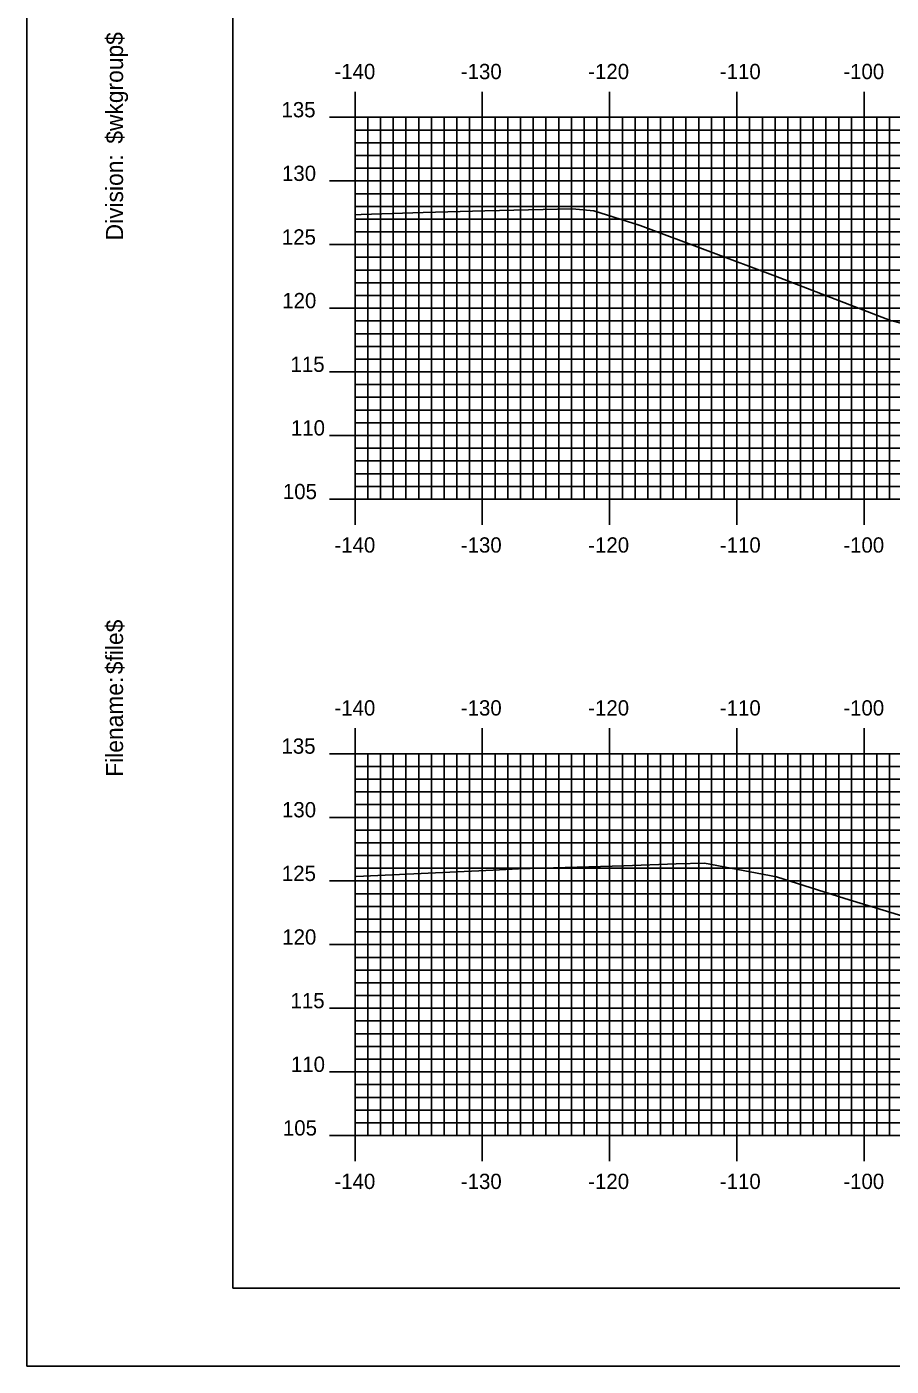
# Model space of a CAD drawing. Extents: x 854681 to 855024, y 366605 to 366825.
# Drawn here: x 854680.8 to 854748.7, y 366604.9 to 366710.2 of the extents above; entities that cross this region are included whole.
import ezdxf

# ---------------------------------------------------------------- set-up
doc = ezdxf.new("R2010")
doc.units = 0
for name, color, linetype in [('BORDER', 7, 'Continuous'), ('H_V ANNOTATION', 7, 'Continuous'), ('M_Roadway_Centerline', 7, 'Continuous'), ('MAJOR', 7, 'Continuous'), ('MINOR', 7, 'Continuous'), ('PLOT BOUNDARY', 7, 'Continuous'), ('S_Roadway_Centerline', 7, 'Continuous')]:
    doc.layers.add(name, color=color, linetype=linetype)

msp = doc.modelspace()

# ---------------------------------------------------------------- linework, layer by layer
at = {"layer": 'BORDER'}
msp.add_lwpolyline([(854696.96, 366611.06), (855016.96, 366611.06), (855016.96, 366821.06), (854696.96, 366821.06)], close=True, dxfattribs=at)
at = {"layer": 'MAJOR'}
for p, q in [((854706.56, 366705.06), (854706.56, 366703.06)), ((854716.56, 366705.06), (854716.56, 366703.06)), ((854726.56, 366705.06), (854726.56, 366703.06)), ((854736.56, 366705.06), (854736.56, 366703.06)), ((854746.56, 366705.06), (854746.56, 366703.06)), ((854704.55, 366703.06), (854706.56, 366703.06)), ((854706.56, 366703.06), (854986.56, 366703.06)), ((854706.56, 366673.06), (854706.56, 366703.06)), ((854706.56, 366673.06), (854706.56, 366703.06)), ((854706.56, 366703.06), (854986.56, 366703.06)), ((854716.56, 366673.06), (854716.56, 366703.06)), ((854726.56, 366673.06), (854726.56, 366703.06)), ((854736.56, 366673.06), (854736.56, 366703.06)), ((854746.56, 366673.06), (854746.56, 366703.06)), ((854704.55, 366698.06), (854706.56, 366698.06)), ((854706.56, 366698.06), (854986.56, 366698.06)), ((854704.55, 366693.06), (854706.56, 366693.06)), ((854706.56, 366693.06), (854986.56, 366693.06)), ((854704.55, 366688.06), (854706.56, 366688.06)), ((854706.56, 366688.06), (854986.56, 366688.06)), ((854704.55, 366683.06), (854706.56, 366683.06)), ((854706.56, 366683.06), (854986.56, 366683.06)), ((854704.55, 366678.06), (854706.56, 366678.06)), ((854706.56, 366678.06), (854986.56, 366678.06)), ((854704.55, 366673.06), (854706.56, 366673.06)), ((854706.56, 366673.06), (854986.56, 366673.06)), ((854706.56, 366673.06), (854986.56, 366673.06)), ((854706.56, 366671.05), (854706.56, 366673.06)), ((854716.56, 366671.05), (854716.56, 366673.06)), ((854726.56, 366671.05), (854726.56, 366673.06)), ((854736.56, 366671.05), (854736.56, 366673.06)), ((854746.56, 366671.05), (854746.56, 366673.06)), ((854706.56, 366655.06), (854706.56, 366653.06)), ((854716.56, 366655.06), (854716.56, 366653.06)), ((854726.56, 366655.06), (854726.56, 366653.06)), ((854736.56, 366655.06), (854736.56, 366653.06)), ((854746.56, 366655.06), (854746.56, 366653.06)), ((854704.55, 366653.06), (854706.56, 366653.06)), ((854706.56, 366653.06), (854986.56, 366653.06)), ((854706.56, 366623.06), (854706.56, 366653.06)), ((854706.56, 366623.06), (854706.56, 366653.06)), ((854706.56, 366653.06), (854986.56, 366653.06)), ((854716.56, 366623.06), (854716.56, 366653.06)), ((854726.56, 366623.06), (854726.56, 366653.06)), ((854736.56, 366623.06), (854736.56, 366653.06)), ((854746.56, 366623.06), (854746.56, 366653.06)), ((854704.55, 366648.06), (854706.56, 366648.06)), ((854706.56, 366648.06), (854986.56, 366648.06)), ((854704.55, 366643.06), (854706.56, 366643.06)), ((854706.56, 366643.06), (854986.56, 366643.06)), ((854704.55, 366638.06), (854706.56, 366638.06)), ((854706.56, 366638.06), (854986.56, 366638.06)), ((854704.55, 366633.06), (854706.56, 366633.06)), ((854706.56, 366633.06), (854986.56, 366633.06)), ((854704.55, 366628.06), (854706.56, 366628.06)), ((854706.56, 366628.06), (854986.56, 366628.06)), ((854704.55, 366623.06), (854706.56, 366623.06)), ((854706.56, 366623.06), (854986.56, 366623.06)), ((854706.56, 366623.06), (854986.56, 366623.06)), ((854706.56, 366621.05), (854706.56, 366623.06)), ((854716.56, 366621.05), (854716.56, 366623.06)), ((854726.56, 366621.05), (854726.56, 366623.06)), ((854736.56, 366621.05), (854736.56, 366623.06)), ((854746.56, 366621.05), (854746.56, 366623.06))]:
    msp.add_line(p, q, dxfattribs=at)
at = {"layer": 'MINOR'}
for p, q in [((854707.56, 366673.06), (854707.56, 366703.06)), ((854708.56, 366673.06), (854708.56, 366703.06)), ((854709.56, 366673.06), (854709.56, 366703.06)), ((854710.56, 366673.06), (854710.56, 366703.06)), ((854711.56, 366673.06), (854711.56, 366703.06)), ((854712.56, 366673.06), (854712.56, 366703.06)), ((854713.56, 366673.06), (854713.56, 366703.06)), ((854714.56, 366673.06), (854714.56, 366703.06)), ((854715.56, 366673.06), (854715.56, 366703.06)), ((854717.56, 366673.06), (854717.56, 366703.06)), ((854718.56, 366673.06), (854718.56, 366703.06)), ((854719.56, 366673.06), (854719.56, 366703.06)), ((854720.56, 366673.06), (854720.56, 366703.06)), ((854721.56, 366673.06), (854721.56, 366703.06)), ((854722.56, 366673.06), (854722.56, 366703.06)), ((854723.56, 366673.06), (854723.56, 366703.06)), ((854724.56, 366673.06), (854724.56, 366703.06)), ((854725.56, 366673.06), (854725.56, 366703.06)), ((854727.56, 366673.06), (854727.56, 366703.06)), ((854728.56, 366673.06), (854728.56, 366703.06)), ((854729.56, 366673.06), (854729.56, 366703.06)), ((854730.56, 366673.06), (854730.56, 366703.06)), ((854731.56, 366673.06), (854731.56, 366703.06)), ((854732.56, 366673.06), (854732.56, 366703.06)), ((854733.56, 366673.06), (854733.56, 366703.06)), ((854734.56, 366673.06), (854734.56, 366703.06)), ((854735.56, 366673.06), (854735.56, 366703.06)), ((854737.56, 366673.06), (854737.56, 366703.06)), ((854738.56, 366673.06), (854738.56, 366703.06)), ((854739.56, 366673.06), (854739.56, 366703.06)), ((854740.56, 366673.06), (854740.56, 366703.06)), ((854741.56, 366673.06), (854741.56, 366703.06)), ((854742.56, 366673.06), (854742.56, 366703.06)), ((854743.56, 366673.06), (854743.56, 366703.06)), ((854744.56, 366673.06), (854744.56, 366703.06)), ((854745.56, 366673.06), (854745.56, 366703.06)), ((854747.56, 366673.06), (854747.56, 366703.06)), ((854748.56, 366673.06), (854748.56, 366703.06)), ((854706.56, 366702.06), (854986.56, 366702.06)), ((854706.56, 366702.06), (854708.56, 366702.06)), ((854706.56, 366701.06), (854986.56, 366701.06)), ((854706.56, 366701.06), (854708.56, 366701.06)), ((854706.56, 366700.06), (854986.56, 366700.06)), ((854706.56, 366700.06), (854708.56, 366700.06)), ((854706.56, 366699.06), (854986.56, 366699.06)), ((854706.56, 366699.06), (854708.56, 366699.06)), ((854706.56, 366697.06), (854986.56, 366697.06)), ((854706.56, 366697.06), (854708.56, 366697.06)), ((854706.56, 366696.06), (854986.56, 366696.06)), ((854706.56, 366696.06), (854708.56, 366696.06)), ((854706.56, 366695.06), (854986.56, 366695.06)), ((854706.56, 366695.06), (854708.56, 366695.06)), ((854706.56, 366694.06), (854986.56, 366694.06)), ((854706.56, 366694.06), (854708.56, 366694.06)), ((854706.56, 366692.06), (854986.56, 366692.06)), ((854706.56, 366692.06), (854708.56, 366692.06)), ((854706.56, 366691.06), (854986.56, 366691.06)), ((854706.56, 366691.06), (854708.56, 366691.06)), ((854706.56, 366690.06), (854986.56, 366690.06)), ((854706.56, 366690.06), (854708.56, 366690.06)), ((854706.56, 366689.06), (854986.56, 366689.06)), ((854706.56, 366689.06), (854708.56, 366689.06)), ((854706.56, 366687.06), (854986.56, 366687.06)), ((854706.56, 366687.06), (854708.56, 366687.06)), ((854706.56, 366686.06), (854986.56, 366686.06)), ((854706.56, 366686.06), (854708.56, 366686.06)), ((854706.56, 366685.06), (854986.56, 366685.06)), ((854706.56, 366685.06), (854708.56, 366685.06)), ((854706.56, 366684.06), (854986.56, 366684.06)), ((854706.56, 366684.06), (854708.56, 366684.06)), ((854706.56, 366682.06), (854986.56, 366682.06)), ((854706.56, 366682.06), (854708.56, 366682.06)), ((854706.56, 366681.06), (854986.56, 366681.06)), ((854706.56, 366681.06), (854708.56, 366681.06)), ((854706.56, 366680.06), (854986.56, 366680.06)), ((854706.56, 366680.06), (854708.56, 366680.06)), ((854706.56, 366679.06), (854986.56, 366679.06)), ((854706.56, 366679.06), (854708.56, 366679.06)), ((854706.56, 366677.06), (854986.56, 366677.06)), ((854706.56, 366677.06), (854708.56, 366677.06)), ((854706.56, 366676.06), (854986.56, 366676.06)), ((854706.56, 366676.06), (854708.56, 366676.06)), ((854706.56, 366675.06), (854986.56, 366675.06)), ((854706.56, 366675.06), (854708.56, 366675.06)), ((854706.56, 366674.06), (854986.56, 366674.06)), ((854706.56, 366674.06), (854708.56, 366674.06)), ((854707.56, 366623.06), (854707.56, 366653.06)), ((854708.56, 366623.06), (854708.56, 366653.06)), ((854709.56, 366623.06), (854709.56, 366653.06)), ((854710.56, 366623.06), (854710.56, 366653.06)), ((854711.56, 366623.06), (854711.56, 366653.06)), ((854712.56, 366623.06), (854712.56, 366653.06)), ((854713.56, 366623.06), (854713.56, 366653.06)), ((854714.56, 366623.06), (854714.56, 366653.06)), ((854715.56, 366623.06), (854715.56, 366653.06)), ((854717.56, 366623.06), (854717.56, 366653.06)), ((854718.56, 366623.06), (854718.56, 366653.06)), ((854719.56, 366623.06), (854719.56, 366653.06)), ((854720.56, 366623.06), (854720.56, 366653.06)), ((854721.56, 366623.06), (854721.56, 366653.06)), ((854722.56, 366623.06), (854722.56, 366653.06)), ((854723.56, 366623.06), (854723.56, 366653.06)), ((854724.56, 366623.06), (854724.56, 366653.06)), ((854725.56, 366623.06), (854725.56, 366653.06)), ((854727.56, 366623.06), (854727.56, 366653.06)), ((854728.56, 366623.06), (854728.56, 366653.06)), ((854729.56, 366623.06), (854729.56, 366653.06)), ((854730.56, 366623.06), (854730.56, 366653.06)), ((854731.56, 366623.06), (854731.56, 366653.06)), ((854732.56, 366623.06), (854732.56, 366653.06)), ((854733.56, 366623.06), (854733.56, 366653.06)), ((854734.56, 366623.06), (854734.56, 366653.06)), ((854735.56, 366623.06), (854735.56, 366653.06)), ((854737.56, 366623.06), (854737.56, 366653.06)), ((854738.56, 366623.06), (854738.56, 366653.06)), ((854739.56, 366623.06), (854739.56, 366653.06)), ((854740.56, 366623.06), (854740.56, 366653.06)), ((854741.56, 366623.06), (854741.56, 366653.06)), ((854742.56, 366623.06), (854742.56, 366653.06)), ((854743.56, 366623.06), (854743.56, 366653.06)), ((854744.56, 366623.06), (854744.56, 366653.06)), ((854745.56, 366623.06), (854745.56, 366653.06)), ((854747.56, 366623.06), (854747.56, 366653.06)), ((854748.56, 366623.06), (854748.56, 366653.06)), ((854706.56, 366652.06), (854986.56, 366652.06)), ((854706.56, 366652.06), (854708.56, 366652.06)), ((854706.56, 366651.06), (854986.56, 366651.06)), ((854706.56, 366651.06), (854708.56, 366651.06)), ((854706.56, 366650.06), (854986.56, 366650.06)), ((854706.56, 366650.06), (854708.56, 366650.06)), ((854706.56, 366649.06), (854986.56, 366649.06)), ((854706.56, 366649.06), (854708.56, 366649.06)), ((854706.56, 366647.06), (854986.56, 366647.06)), ((854706.56, 366647.06), (854708.56, 366647.06)), ((854706.56, 366646.06), (854986.56, 366646.06)), ((854706.56, 366646.06), (854708.56, 366646.06)), ((854706.56, 366645.06), (854986.56, 366645.06)), ((854706.56, 366645.06), (854708.56, 366645.06)), ((854706.56, 366644.06), (854986.56, 366644.06)), ((854706.56, 366644.06), (854708.56, 366644.06)), ((854706.56, 366642.06), (854986.56, 366642.06)), ((854706.56, 366642.06), (854708.56, 366642.06)), ((854706.56, 366641.06), (854986.56, 366641.06)), ((854706.56, 366641.06), (854708.56, 366641.06)), ((854706.56, 366640.06), (854986.56, 366640.06)), ((854706.56, 366640.06), (854708.56, 366640.06)), ((854706.56, 366639.06), (854986.56, 366639.06)), ((854706.56, 366639.06), (854708.56, 366639.06)), ((854706.56, 366637.06), (854986.56, 366637.06)), ((854706.56, 366637.06), (854708.56, 366637.06)), ((854706.56, 366636.06), (854986.56, 366636.06)), ((854706.56, 366636.06), (854708.56, 366636.06)), ((854706.56, 366635.06), (854986.56, 366635.06)), ((854706.56, 366635.06), (854708.56, 366635.06)), ((854706.56, 366634.06), (854986.56, 366634.06)), ((854706.56, 366634.06), (854708.56, 366634.06)), ((854706.56, 366632.06), (854986.56, 366632.06)), ((854706.56, 366632.06), (854708.56, 366632.06)), ((854706.56, 366631.06), (854986.56, 366631.06)), ((854706.56, 366631.06), (854708.56, 366631.06)), ((854706.56, 366630.06), (854986.56, 366630.06)), ((854706.56, 366630.06), (854708.56, 366630.06)), ((854706.56, 366629.06), (854986.56, 366629.06)), ((854706.56, 366629.06), (854708.56, 366629.06)), ((854706.56, 366627.06), (854986.56, 366627.06)), ((854706.56, 366627.06), (854708.56, 366627.06)), ((854706.56, 366626.06), (854986.56, 366626.06)), ((854706.56, 366626.06), (854708.56, 366626.06)), ((854706.56, 366625.06), (854986.56, 366625.06)), ((854706.56, 366625.06), (854708.56, 366625.06)), ((854706.56, 366624.06), (854986.56, 366624.06)), ((854706.56, 366624.06), (854708.56, 366624.06))]:
    msp.add_line(p, q, dxfattribs=at)
at = {"layer": 'PLOT BOUNDARY'}
msp.add_lwpolyline([(854680.77, 366604.94), (855020.77, 366604.94), (855020.77, 366824.94), (854680.77, 366824.94)], close=True, dxfattribs=at)
at = {"layer": 'S_Roadway_Centerline'}
for points in [[(854706.56, 366695.4), (854707.05, 366695.43), (854711.9, 366695.57), (854716.76, 366695.7), (854723.61, 366695.88), (854725.31, 366695.71), (854728.96, 366694.56), (854739.6, 366690.58), (854748.62, 366687.09), (854751.07, 366686.48)], [(854706.56, 366643.4), (854706.64, 366643.4), (854717.4, 366643.91), (854719.41, 366644.02), (854727.67, 366644.24), (854731.78, 366644.4), (854734.01, 366644.45), (854739.67, 366643.38), (854745.03, 366641.68), (854757.44, 366637.9)]]:
    msp.add_lwpolyline(points, dxfattribs=at)

# ---------------------------------------------------------------- texts
at = {"layer": 'BORDER'}
for s, p in [('$wkgroup$', (854688.33, 366700.99)), ('Division:', (854688.33, 366693.39)), ('$file$', (854688.33, 366659.31)), ('Filename:', (854688.33, 366651.25))]:
    msp.add_text(s, height=1.339, rotation=90, dxfattribs=at).set_placement(p)
at = {"layer": 'H_V ANNOTATION'}
for s, p in [('-140', (854704.94, 366706.06)), ('-130', (854714.87, 366706.06)), ('-120', (854724.88, 366706.06)), ('-110', (854735.22, 366706.06)), ('-100', (854744.92, 366706.06)), ('135', (854700.78, 366703.06)), ('130', (854700.82, 366698.06)), ('125', (854700.81, 366693.06)), ('120', (854700.84, 366688.06)), ('115', (854701.49, 366683.06)), ('110', (854701.52, 366678.06)), ('105', (854700.89, 366673.06)), ('-140', (854704.94, 366668.86)), ('-130', (854714.87, 366668.86)), ('-120', (854724.88, 366668.86)), ('-110', (854735.22, 366668.86)), ('-100', (854744.92, 366668.86)), ('-140', (854704.94, 366656.06)), ('-130', (854714.87, 366656.06)), ('-120', (854724.88, 366656.06)), ('-110', (854735.22, 366656.06)), ('-100', (854744.92, 366656.06)), ('135', (854700.78, 366653.06)), ('130', (854700.82, 366648.06)), ('125', (854700.81, 366643.06)), ('120', (854700.84, 366638.06)), ('115', (854701.49, 366633.06)), ('110', (854701.52, 366628.06)), ('105', (854700.89, 366623.06)), ('-140', (854704.94, 366618.86)), ('-130', (854714.87, 366618.86)), ('-120', (854724.88, 366618.86)), ('-110', (854735.22, 366618.86)), ('-100', (854744.92, 366618.86))]:
    msp.add_text(s, height=1.2, dxfattribs=at).set_placement(p)
at = {"layer": 'M_Roadway_Centerline'}
for s, p in [('C', (854707.04, 366695.43)), ('L', (854707.05, 366695.42)), ('C', (854719.41, 366644.02)), ('L', (854719.41, 366644.01))]:
    msp.add_text(s, height=0.0146, dxfattribs=at).set_placement(p)
at = {"layer": 'MAJOR'}
for p in [(854706.55, 366673.06), (854706.55, 366623.06)]:
    msp.add_text('-', height=0.012, dxfattribs=at).set_placement(p)

doc.saveas('drawing.dxf')
